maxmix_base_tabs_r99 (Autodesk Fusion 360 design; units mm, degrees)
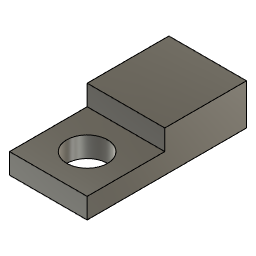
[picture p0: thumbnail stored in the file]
sketch "Sketch1" plane through (0, 0, 0) normal (0, 0, 1) x axis (1, 0, 0)
  line L1 (1.9, 7.8) -> (-1.9, 7.8)
  line L2 (1.9, 0) -> (1.9, 7.8)
  line L3 (-1.9, 0) -> (1.9, 0)
  line L4 (-1.9, 7.8) -> (-1.9, 0)
  line L5 (1.9, 3.8) -> (-1.9, 3.8)
  line L6 (0, 0) -> (0, 3.8)
  circle C1 centre (0, 1.9) radius 1
  point P1 (0, 0)
  point P6 (-1.9, 3.8)
  point P7 (1.9, 3.8)
  point P8 (0, 3.8)
  point P9 (0, 0)
  point P10 (0, 1.9)
  point P2 (-1.9, 7.8)
  point P3 (1.9, 7.8)
  point P5 (-1.9, 0)
  horizontal L1
  vertical L2
  horizontal L3
  vertical L4
  midpoint P1 L3
  coincident L4 P6
  coincident L2 P7
  perpendicular L2 L5
  midpoint L5 P8
  coincident P1 P9
  coincident L6 P10
  dimension "d1" distance P2 P3 = 3.8
  dimension "d2" distance P2 P5 = 7.8
  dimension "d3" diameter C1 = 2
  dimension "d4" distance P1 P10 = 1.9
  dimension "d10" distance L5 P10 = 1.9 (= "d4")
extrude "Extrude1" new body sketch "Sketch1" profile of L2 L3 L4 L5 C1 along normal blind 1
extrude "Extrude2" add sketch "Sketch1" profile of L1 L2 L4 L5 along normal blind 2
